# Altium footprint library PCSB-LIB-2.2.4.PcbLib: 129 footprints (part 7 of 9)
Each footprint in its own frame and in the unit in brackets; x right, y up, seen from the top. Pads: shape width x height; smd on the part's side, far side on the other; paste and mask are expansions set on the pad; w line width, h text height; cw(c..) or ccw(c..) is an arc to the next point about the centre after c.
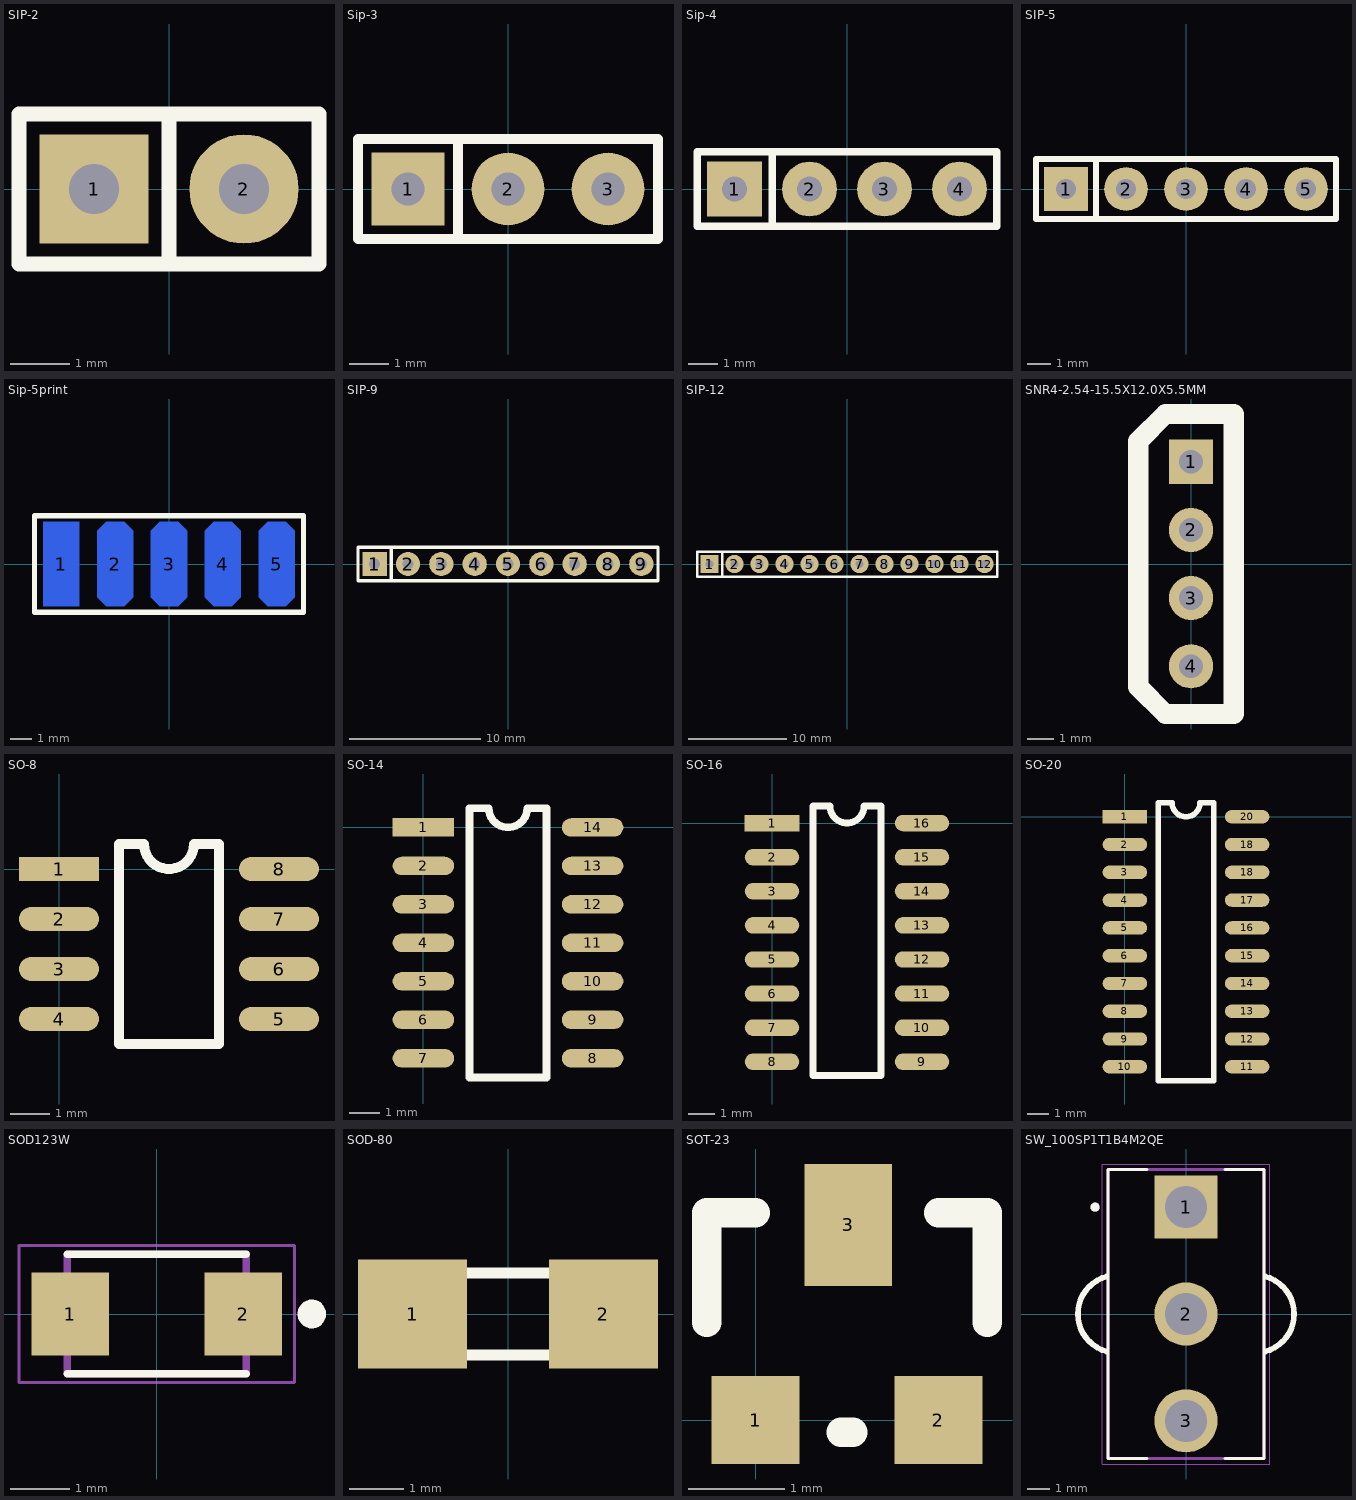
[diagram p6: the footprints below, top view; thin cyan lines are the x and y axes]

## SIP-2 [mm]
pads (2):
  rect 1.85x1.85 hole 0.85: 1(-1.27,0)
  round 1.85 hole 0.85: 2(1.27,0)
Top Overlay:
  lines w0.254: 0,-1.27 0,1.27 ; -2.54,-1.27 -2.54,1.27 2.54,1.27 2.54,-1.27 -2.54,-1.27

## Sip-3 [mm]
pads (3):
  rect 1.85x1.85 hole 0.85: 1(-2.54,0)
  round 1.85 hole 0.85: 2(0,0) 3(2.54,0)
Top Overlay:
  lines w0.254: -1.27,-1.27 -1.27,1.27 ; -3.81,-1.27 -3.81,1.27 3.81,1.27 3.81,-1.27 -3.81,-1.27

## Sip-4 [mm]
pads (4):
  rect 1.85x1.85 hole 0.85: 1(-3.81,0)
  round 1.85 hole 0.85: 2(-1.27,0) 3(1.27,0) 4(3.81,0)
Top Overlay:
  lines w0.254: -2.54,-1.27 -2.54,1.27 ; -5.08,-1.27 -5.08,1.27 5.08,1.27 5.08,-1.27 -5.08,-1.27

## SIP-5 [mm]
pads (5):
  rect 1.85x1.85 hole 0.85: 1(-5.08,0)
  round 1.85 hole 0.85: 2(-2.54,0) 3(0,0) 4(2.54,0) 5(5.08,0)
Top Overlay:
  lines w0.254: -3.81,-1.27 -3.81,1.27 ; -6.35,-1.27 6.35,-1.27 6.35,1.27 -6.35,1.27 -6.35,-1.27

## Sip-5print [mm]
pads (5):
  rect 1.7x4 smd far side: 1(-5.08,0)
  oct 1.7x4 smd far side: 2(-2.54,0) 3(0,0) 4(2.54,0) 5(5.08,0)
Top Overlay:
  lines w0.254: -6.35,-2.286 -6.35,2.286 6.35,2.286 6.35,-2.286 -6.35,-2.286

## SIP-9 [mm]
pads (9):
  rect 1.85x1.85 hole 0.85: 1(-10.16,0)
  round 1.85 hole 0.85: 2(-7.62,0) 3(-5.08,0) 4(-2.54,0) 5(0,0) 6(2.54,0) 7(5.08,0) 8(7.62,0) 9(10.16,0)
Top Overlay:
  lines w0.254: -8.89,-1.27 -8.89,1.27 ; -11.43,-1.27 11.43,-1.27 11.43,1.27 -11.43,1.27 -11.43,-1.27

## SIP-12 [mm]
pads (12):
  rect 1.85x1.85 hole 0.85: 1(-13.97,0)
  round 1.85 hole 0.85: 2(-11.43,0) 3(-8.89,0) 4(-6.35,0) 5(-3.81,0) 6(-1.27,0) 7(1.27,0) 8(3.81,0) 9(6.35,0) 10(8.89,0) 11(11.43,0) 12(13.97,0)
Top Overlay:
  lines w0.254: -12.7,-1.27 -12.7,1.27 ; -15.24,-1.27 15.24,-1.27 15.24,1.27 -15.24,1.27 -15.24,-1.27

## SNR4-2.54-15.5X12.0X5.5MM [mil]
pads (4):
  rect 65x65 hole 35: 1(0,150)
  round 65 hole 35: 2(0,50) 3(0,-50) 4(0,-150)
Top Overlay:
  lines w29.53: -77.4,-180 -37.4,-220 62.6,-220 62.6,220 -37.4,220 -77.4,180 -77.4,-180

## SO-8 [mil]
pads (8):
  rect 80x24 smd: 1(0,0)
  oval 80x24 smd: 2(0,-50) 3(0,-100) 4(0,-150) 5(220,-150) 6(220,-100) 7(220,-50) 8(220,0)
Top Overlay:
  lines w10: 60,-175 60,25 85,25 ccw(c110,25) 135,25 160,25 160,-175 60,-175

## SO-14 [mil]
pads (14):
  rect 80x24 smd: 1(0,0)
  oval 80x24 smd: 2(0,-50) 3(0,-100) 4(0,-150) 5(0,-200) 6(0,-250) 7(0,-300) 8(220,-300) 9(220,-250) 10(220,-200) 11(220,-150) 12(220,-100) 13(220,-50) 14(220,0)
Top Overlay:
  lines w10: 60,-325 60,25 85,25 ccw(c110,25) 135,25 160,25 160,-325 60,-325

## SO-16 [mil]
pads (16):
  rect 80x24 smd: 1(0,0)
  oval 80x24 smd: 2(0,-50) 3(0,-100) 4(0,-150) 5(0,-200) 6(0,-250) 7(0,-300) 8(0,-350) 9(220,-350) 10(220,-300) 11(220,-250) 12(220,-200) 13(220,-150) 14(220,-100) 15(220,-50) 16(220,0)
Top Overlay:
  lines w10: 60,-370 160,-370 160,25 135,25 cw(c110,25) 85,25 60,25 60,-370

## SO-20 [mil]
pads (20):
  rect 80x24 smd: 1(0,0)
  oval 80x24 smd: 2(0,-50) 3(0,-100) 4(0,-150) 5(0,-200) 6(0,-250) 7(0,-300) 8(0,-350) 9(0,-400) 10(0,-450) 11(220,-450) 12(220,-400) 13(220,-350) 14(220,-300) 15(220,-250) 16(220,-200) 17(220,-150) 18(220,-100) 18(220,-50) 20(220,0)
Top Overlay:
  lines w10: 60,-475 60,25 85,25 ccw(c110,25) 135,25 160,25 160,-475 60,-475

## SOD123W [mm]
pads (2):
  rect 1.3x1.4 smd: 1(-1.45,0) 2(1.45,0)
Top Overlay:
  circle w0.24: c2.6,0 r0.12
  lines w0.127: -1.5,-1 1.5,-1 ; -1.5,1 1.5,1
Mechanical 13:
  lines w0.127: -1.5,-1 -1.5,1 1.5,1 1.5,-1 -1.5,-1
Mechanical 15:
  lines w0.05: -2.31,-1.15 2.31,-1.15 2.31,1.15 -2.31,1.15 -2.31,-1.15

## SOD-80 [mm]
height 1.5
pads (2):
  rect 2x2 smd: 1(-1.75,0) 2(1.75,0)
Top Overlay:
  lines w0.2: 1,-0.75 1,0.75 ; -1.75,-0.75 -1.75,0.75 1.75,0.75 1.75,-0.75 -1.75,-0.75

## SOT-23 [mil]
pads (3):
  rect 36x36 smd: 1(0,0) 2(75,0)
  rect 36x50 smd: 3(38,80)
Top Overlay:
  lines w12: -20,40 -20,85 0,85 ; 35,-5 40,-5 ; 75,85 95,85 95,40

## SW_100SP1T1B4M2QE [mm]
pads (3):
  rect 2.775x2.775 hole 1.85: 1(0,4.7)
  round 2.775 hole 1.85: 2(0,0) 3(0,-4.7)
Top Overlay:
  circle w0.2: c-4,4.7 r0.1
  lines w0.127: -1.71,-6.35 -3.43,-6.35 -3.43,6.35 -1.71,6.35 ; 1.71,-6.35 3.43,-6.35 3.43,6.35 1.71,6.35
  lines w0.254: -3.49,-1.65 cw(c-3.048,0) -3.49,1.65 ; 3.49,-1.65 ccw(c3.048,0) 3.49,1.65
Mechanical 13:
  circle w0.2: c-4,4.7 r0.1
  lines w0.127: -3.43,-6.35 -3.43,6.35 3.43,6.35 3.43,-6.35 -3.43,-6.35
Mechanical 15:
  lines w0.05: -3.68,-6.6 -3.68,6.6 3.68,6.6 3.68,-6.6 -3.68,-6.6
